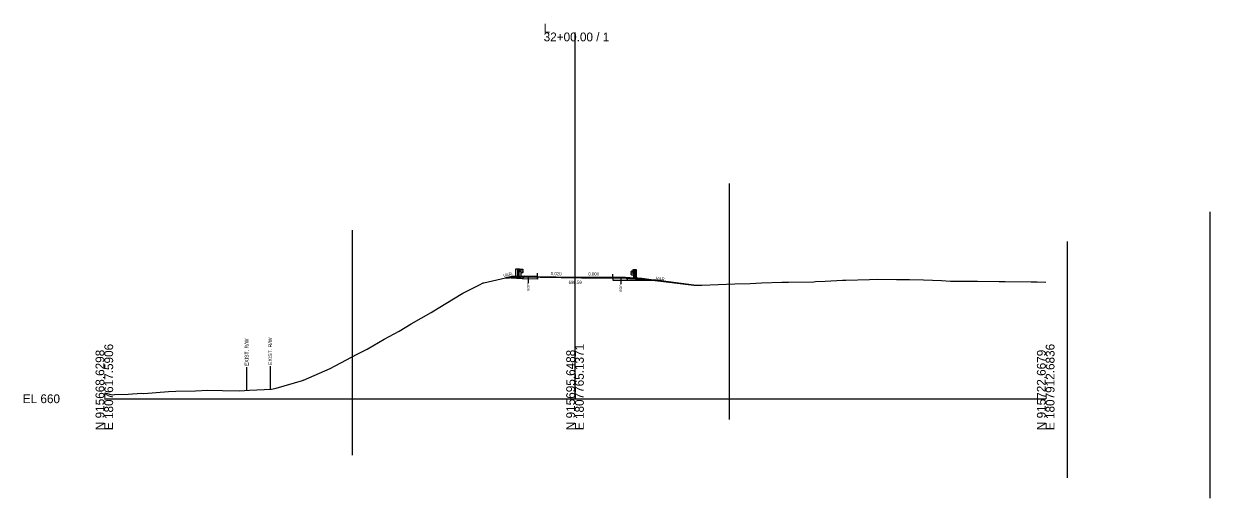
# Model space of a CAD drawing. Extents: x -26 to 1352, y -510 to 9596.
# Drawn here: x 974.3 to 1352.4, y 7968.3 to 8119.4 of the extents above; entities that cross this region are included whole.
import ezdxf

# ---------------------------------------------------------------- set-up
doc = ezdxf.new("R2010")
doc.units = 0
for name, color, linetype in [('Exist Cross Section Cell', 7, 'Continuous'), ('Exist XS Center Line Elevation Label', 7, 'Continuous'), ('Exist XS Ground Line', 7, 'Continuous'), ('Old_Level_10', 7, 'Continuous'), ('Prop XS Ditch Slope Text', 7, 'Continuous'), ('Prop XS Dump Level', 7, 'Continuous'), ('Prop XS Earthwork Shape', 7, 'Continuous'), ('Prop XS EOT Tick Mark', 7, 'Continuous'), ('Prop XS Exc Vertical Line 1', 7, 'Continuous'), ('Prop XS Exc Vertical Line 2', 7, 'Continuous'), ('Prop XS Exc Vertical Line 3', 7, 'Continuous'), ('Prop XS Exc Vertical Line 4', 7, 'Continuous'), ('Prop XS Finish Grade', 7, 'Continuous'), ('Prop XS Finish Grade Earthwork', 7, 'Continuous'), ('Prop XS Finish Grade Paved Shoulder', 7, 'Continuous'), ('Prop XS Finish Grade Pavement', 7, 'Continuous'), ('Prop XS Guardrail', 7, 'Continuous'), ('Prop XS Pvmt Edge Slope', 7, 'Continuous'), ('Prop XS SE Text', 7, 'Continuous'), ('Prop XS Subgrade Earthwork', 7, 'Continuous'), ('Scratch_Level_6', 7, 'Continuous')]:
    doc.layers.add(name, color=color, linetype=linetype)

msp = doc.modelspace()

# ---------------------------------------------------------------- linework, layer by layer
at = {"layer": 'Exist Cross Section Cell'}
for p, q in [((1150, 8000), (1150, 8116.63)), ((1000, 8000), (1150, 8000)), ((1150, 8000), (1300, 8000))]:
    msp.add_line(p, q, dxfattribs=at)
at = {"layer": 'Exist XS Ground Line'}
msp.add_lwpolyline([(1000, 8001.87), (1002.45, 8001.25), (1003.25, 8001.33), (1007.61, 8001.46), (1011.84, 8001.81), (1012.62, 8001.65), (1020.43, 8002.35), (1022.78, 8002.43), (1029.03, 8002.53), (1032.95, 8002.72), (1037.62, 8002.61), (1043.11, 8002.52), (1046.21, 8002.72), (1053.28, 8003.05), (1054.8, 8003.35), (1063.12, 8005.82), (1063.4, 8005.9), (1063.45, 8005.92), (1071.99, 8009.61), (1073.61, 8010.46), (1080.58, 8014.16), (1083.78, 8015.79), (1089.18, 8018.94), (1093.95, 8021.58), (1097.77, 8023.82), (1104.11, 8027.48), (1106.36, 8028.84), (1114.28, 8033.66), (1119.55, 8036.25), (1120.71, 8036.87), (1120.92, 8036.92), (1127.82, 8038.47), (1128.23, 8038.51), (1128.56, 8038.52), (1128.66, 8038.53), (1128.81, 8038.53), (1128.84, 8038.54), (1129.09, 8038.55), (1129.56, 8038.58), (1130.68, 8038.64), (1135.06, 8038.88), (1135.2, 8038.87), (1136.36, 8038.84), (1136.7, 8038.83), (1137.13, 8038.83), (1138.65, 8038.78), (1138.91, 8038.77), (1139.18, 8038.77), (1140.62, 8038.76), (1141.45, 8038.76), (1143.47, 8038.71), (1143.99, 8038.69), (1145.62, 8038.66), (1146.54, 8038.65), (1147.87, 8038.63), (1149.07, 8038.62), (1149.52, 8038.6), (1149.89, 8038.59), (1150, 8038.59), (1151.18, 8038.57), (1151.61, 8038.57), (1152.05, 8038.56), (1154.15, 8038.56), (1154.49, 8038.56), (1156.7, 8038.56), (1158.51, 8038.54), (1159.24, 8038.53), (1161.26, 8038.54), (1161.97, 8038.55), (1161.97, 8038.55), (1162.87, 8038.55), (1164.6, 8038.55), (1165.66, 8038.47), (1166.8, 8038.39), (1167.41, 8038.34), (1169.23, 8038.22), (1175.51, 8037.67), (1187.86, 8036.19), (1190.39, 8036.21), (1195.61, 8036.38), (1200.88, 8036.6), (1205.78, 8036.74), (1209.47, 8036.87), (1215.94, 8037.1), (1218.07, 8037.1), (1226.11, 8037.27), (1226.66, 8037.3), (1229.67, 8037.46), (1235.25, 8037.79), (1236.27, 8037.79), (1243.85, 8037.99), (1246.44, 8038.06), (1252.44, 8038.03), (1256.61, 8037.96), (1261.03, 8037.88), (1266.77, 8037.69), (1269.62, 8037.5), (1276.94, 8037.47), (1278.22, 8037.46), (1285.19, 8037.34), (1286.81, 8037.31), (1287.11, 8037.3), (1295.4, 8037.21), (1297.27, 8037.19), (1300, 8037.13)], dxfattribs=at)
at = {"layer": 'Old_Level_10'}
for p, q in [((1135.06, 8038.88), (1135.06, 8036.83)), ((1164.6, 8038.55), (1164.6, 8036.5)), ((1045.35, 8010.06), (1045.35, 8002.66)), ((1052.86, 8010.43), (1052.86, 8003.03))]:
    msp.add_line(p, q, dxfattribs=at)
at = {"layer": 'Prop XS Dump Level'}
for p, q in [((1150, 8038.6), (1138, 8038.84)), ((1138, 8038.84), (1138, 8038.8)), ((1162, 8038.6), (1150, 8038.6)), ((1162, 8038.55), (1162, 8038.6))]:
    msp.add_line(p, q, dxfattribs=at)
msp.add_lwpolyline([(1138, 8038.8), (1138.65, 8038.78), (1138.91, 8038.77), (1139.18, 8038.77), (1140.62, 8038.76), (1141.45, 8038.76), (1143.47, 8038.71), (1143.99, 8038.69), (1145.62, 8038.66), (1146.54, 8038.65), (1147.87, 8038.63), (1149.07, 8038.62), (1149.52, 8038.6), (1149.89, 8038.59), (1150, 8038.59), (1151.18, 8038.57), (1151.61, 8038.57), (1152.05, 8038.56), (1154.15, 8038.56), (1154.49, 8038.56), (1156.7, 8038.56), (1158.51, 8038.54), (1159.24, 8038.53), (1161.26, 8038.54), (1161.97, 8038.55), (1161.97, 8038.55), (1162, 8038.55)], dxfattribs=at)
at = {"layer": 'Prop XS Earthwork Shape'}
for points in [[(1128.84, 8038.54), (1129.09, 8038.55), (1129.56, 8038.58), (1130.68, 8038.64), (1135.06, 8038.88), (1135.2, 8038.87), (1136.36, 8038.84), (1136.7, 8038.83), (1137.13, 8038.83), (1138, 8038.8), (1138, 8038.05), (1133.1, 8038.15), (1127.82, 8038.47), (1128.23, 8038.51), (1128.56, 8038.52), (1128.66, 8038.53), (1128.81, 8038.53)], [(1138, 8038.05), (1133.1, 8038.15), (1127.82, 8038.47), (1128.23, 8038.51), (1128.56, 8038.52), (1128.66, 8038.53), (1128.81, 8038.53), (1128.84, 8038.54), (1129.09, 8038.55), (1129.56, 8038.58), (1130.68, 8038.64), (1135.06, 8038.88), (1135.2, 8038.87), (1136.36, 8038.84), (1136.7, 8038.83), (1137.13, 8038.83), (1138, 8038.8)], [(1128.81, 8038.53), (1128.84, 8038.54), (1129.09, 8038.55), (1129.56, 8038.58), (1130.68, 8038.64), (1135.06, 8038.88), (1135.2, 8038.87), (1136.36, 8038.84), (1136.7, 8038.83), (1137.13, 8038.83), (1138, 8038.8), (1138, 8038.05), (1133.1, 8038.15), (1127.82, 8038.47), (1128.23, 8038.51), (1128.56, 8038.52), (1128.66, 8038.53)], [(1128.81, 8038.53), (1128.84, 8038.54), (1129.09, 8038.55), (1129.56, 8038.58), (1130.68, 8038.64), (1135.06, 8038.88), (1135.2, 8038.87), (1136.36, 8038.84), (1136.7, 8038.83), (1137.13, 8038.83), (1138, 8038.8), (1138, 8038.05), (1133.1, 8038.15), (1127.82, 8038.47), (1128.23, 8038.51), (1128.56, 8038.52), (1128.66, 8038.53)], [(1128.84, 8038.54), (1129.09, 8038.55), (1129.56, 8038.58), (1130.68, 8038.64), (1135.06, 8038.88), (1135.2, 8038.87), (1136.36, 8038.84), (1136.7, 8038.83), (1137.13, 8038.83), (1138, 8038.8), (1138, 8038.05), (1133.1, 8038.15), (1127.82, 8038.47), (1128.23, 8038.51), (1128.56, 8038.52), (1128.66, 8038.53), (1128.81, 8038.53)], [(1162, 8038.55), (1162, 8037.81), (1166.92, 8037.81), (1173.92, 8037.81), (1169.23, 8038.22), (1167.41, 8038.34), (1166.8, 8038.39), (1165.66, 8038.47), (1164.6, 8038.55), (1162.87, 8038.55)], [(1162, 8038.55), (1162, 8037.81), (1166.92, 8037.81), (1173.92, 8037.81), (1169.23, 8038.22), (1167.41, 8038.34), (1166.8, 8038.39), (1165.66, 8038.47), (1164.6, 8038.55), (1162.87, 8038.55)], [(1166.92, 8037.81), (1173.92, 8037.81), (1169.23, 8038.22), (1167.41, 8038.34), (1166.8, 8038.39), (1165.66, 8038.47), (1164.6, 8038.55), (1162.87, 8038.55), (1162, 8038.55), (1162, 8037.81)], [(1162, 8038.55), (1162, 8037.81), (1166.92, 8037.81), (1173.92, 8037.81), (1169.23, 8038.22), (1167.41, 8038.34), (1166.8, 8038.39), (1165.66, 8038.47), (1164.6, 8038.55), (1162.87, 8038.55)], [(1175.51, 8037.67), (1187.86, 8036.19), (1175.79, 8037.81), (1173.92, 8037.81)], [(1175.79, 8037.81), (1187.86, 8036.19), (1175.51, 8037.67), (1173.92, 8037.81)], [(1175.79, 8037.81), (1187.86, 8036.19), (1175.51, 8037.67), (1173.92, 8037.81)], [(1175.79, 8037.81), (1187.86, 8036.19), (1175.51, 8037.67), (1173.92, 8037.81)], [(1173.92, 8037.81), (1175.79, 8037.81), (1187.86, 8036.19), (1175.51, 8037.67)]]:
    msp.add_lwpolyline(points, close=True, dxfattribs=at)
at = {"layer": 'Prop XS EOT Tick Mark'}
for p, q in [((1138, 8038.97), (1138, 8039.97)), ((1162, 8038.73), (1162, 8039.73))]:
    msp.add_line(p, q, dxfattribs=at)
at = {"layer": 'Prop XS Exc Vertical Line 1'}
msp.add_line((1079.04, 7981.99), (1079.04, 8053.65), dxfattribs=at)
at = {"layer": 'Prop XS Exc Vertical Line 2'}
msp.add_line((1199.25, 7993.36), (1199.25, 8068.59), dxfattribs=at)
at = {"layer": 'Prop XS Exc Vertical Line 3'}
msp.add_line((1306.96, 7974.83), (1306.96, 8050.07), dxfattribs=at)
at = {"layer": 'Prop XS Exc Vertical Line 4'}
msp.add_line((1352.44, 7968.31), (1352.44, 8059.51), dxfattribs=at)
at = {"layer": 'Prop XS Finish Grade'}
for p, q in [((1129.44, 8038.87), (1127.82, 8038.47)), ((1132.43, 8038.99), (1129.44, 8038.87)), ((1132.43, 8038.99), (1130, 8038.89)), ((1134, 8039.05), (1132.43, 8038.99)), ((1166, 8038.73), (1167.57, 8038.64)), ((1167.57, 8038.64), (1170, 8038.49)), ((1170, 8038.49), (1171.32, 8038.41)), ((1171.32, 8038.41), (1175.79, 8037.81))]:
    msp.add_line(p, q, dxfattribs=at)
at = {"layer": 'Prop XS Finish Grade Earthwork'}
msp.add_line((1175.79, 8037.81), (1187.86, 8036.19), dxfattribs=at)
at = {"layer": 'Prop XS Finish Grade Paved Shoulder'}
for p, q in [((1138, 8038.97), (1134, 8039.05)), ((1162, 8038.73), (1166, 8038.73))]:
    msp.add_line(p, q, dxfattribs=at)
at = {"layer": 'Prop XS Finish Grade Pavement'}
for p, q in [((1138, 8038.97), (1150, 8038.73)), ((1150, 8038.73), (1162, 8038.73))]:
    msp.add_line(p, q, dxfattribs=at)
at = {"layer": 'Prop XS Guardrail'}
for p, q in [((1131.15, 8038.92), (1131.15, 8041.42)), ((1131.15, 8041.42), (1131.65, 8041.42)), ((1131.65, 8041.42), (1131.65, 8038.92)), ((1131.65, 8041.42), (1132.15, 8041.42)), ((1132.15, 8040.29), (1131.65, 8040.29)), ((1132.15, 8041.42), (1132.44, 8041.22)), ((1132.44, 8041.1), (1132.15, 8040.9)), ((1132.15, 8040.9), (1132.15, 8040.81)), ((1132.15, 8040.81), (1132.44, 8040.61)), ((1132.44, 8040.49), (1132.15, 8040.29)), ((1132.44, 8041.22), (1132.47, 8041.16)), ((1132.47, 8041.16), (1132.44, 8041.1)), ((1132.44, 8040.61), (1132.47, 8040.55)), ((1132.47, 8040.55), (1132.44, 8040.49)), ((1168.32, 8040.86), (1168.29, 8040.8)), ((1168.29, 8040.8), (1168.32, 8040.74)), ((1168.32, 8040.24), (1168.29, 8040.18)), ((1168.29, 8040.18), (1168.32, 8040.12)), ((1168.61, 8041.06), (1168.32, 8040.86)), ((1168.32, 8040.74), (1168.61, 8040.54)), ((1168.61, 8040.44), (1168.32, 8040.24)), ((1168.32, 8040.12), (1168.61, 8039.92)), ((1169.11, 8041.06), (1168.61, 8041.06)), ((1168.61, 8040.54), (1168.61, 8040.44)), ((1168.61, 8039.92), (1169.11, 8039.92)), ((1169.61, 8041.06), (1169.11, 8041.06)), ((1169.11, 8041.06), (1169.11, 8038.56)), ((1169.61, 8038.56), (1169.61, 8041.06))]:
    msp.add_line(p, q, dxfattribs=at)
at = {"layer": 'Prop XS Pvmt Edge Slope'}
for p, q in [((1134, 8039.05), (1133.1, 8038.15)), ((1166, 8038.73), (1166.92, 8037.81))]:
    msp.add_line(p, q, dxfattribs=at)
at = {"layer": 'Prop XS Subgrade Earthwork'}
for p, q in [((1133.1, 8038.15), (1127.82, 8038.47)), ((1138, 8038.05), (1133.1, 8038.15)), ((1138, 8038.05), (1138, 8038.8)), ((1162, 8038.55), (1162, 8037.81)), ((1162, 8037.81), (1166.92, 8037.81)), ((1166.92, 8037.81), (1175.79, 8037.81))]:
    msp.add_line(p, q, dxfattribs=at)
at = {"layer": 'Scratch_Level_6'}
for p, q in [((1132.22, 8038.73), (1132.22, 8041.23)), ((1132.22, 8041.23), (1132.72, 8041.23)), ((1132.72, 8041.23), (1132.72, 8038.73)), ((1132.72, 8041.23), (1133.22, 8041.23)), ((1133.22, 8040.1), (1132.72, 8040.1)), ((1133.22, 8041.23), (1133.51, 8041.03)), ((1133.51, 8040.91), (1133.22, 8040.71)), ((1133.22, 8040.71), (1133.22, 8040.62)), ((1133.22, 8040.62), (1133.51, 8040.42)), ((1133.51, 8040.3), (1133.22, 8040.1)), ((1133.51, 8041.03), (1133.54, 8040.97)), ((1133.54, 8040.97), (1133.51, 8040.91)), ((1133.51, 8040.42), (1133.54, 8040.36)), ((1133.54, 8040.36), (1133.51, 8040.3)), ((1167.82, 8040.45), (1167.79, 8040.39)), ((1167.79, 8040.39), (1167.82, 8040.33)), ((1167.82, 8039.83), (1167.79, 8039.77)), ((1167.79, 8039.77), (1167.82, 8039.71)), ((1168.11, 8040.65), (1167.82, 8040.45)), ((1167.82, 8040.33), (1168.11, 8040.13)), ((1168.11, 8040.03), (1167.82, 8039.83)), ((1167.82, 8039.71), (1168.11, 8039.51)), ((1168.61, 8040.65), (1168.11, 8040.65)), ((1168.11, 8040.13), (1168.11, 8040.03)), ((1168.11, 8039.51), (1168.61, 8039.51)), ((1169.11, 8040.65), (1168.61, 8040.65)), ((1168.61, 8040.65), (1168.61, 8038.15)), ((1169.11, 8038.15), (1169.11, 8040.65))]:
    msp.add_line(p, q, dxfattribs=at)

# ---------------------------------------------------------------- texts
at = {"layer": 'Exist Cross Section Cell'}
for s, p in [('L', (1140, 8116.63)), ('32+00.00 / 1', (1140, 8113.83)), ('EL 660', (974, 7998.6))]:
    msp.add_text(s, height=2.8, dxfattribs=at).set_placement(p)
for s, p in [('E 1807617.5906', (1002.8, 7990)), ('E 1807765.1371', (1152.8, 7990)), ('E 1807912.6836', (1302.8, 7990)), ('N 915668.6298', (1000, 7990)), ('N 915695.6488', (1150, 7990)), ('N 915722.6679', (1300, 7990))]:
    msp.add_text(s, height=2.8, rotation=90, dxfattribs=at).set_placement(p)
at = {"layer": 'Exist XS Center Line Elevation Label'}
msp.add_text('698.59', height=1, dxfattribs=at).set_placement((1147.95, 8036.59))
at = {"layer": 'Old_Level_10'}
for s, height, p in [('EOP', 0.787, (1135.46, 8034.43)), ('EOP', 0.787, (1164.99, 8034.1)), ('EXIST. R/W', 1.181, (1045.94, 8010.37)), ('EXIST. R/W', 1.181, (1053.45, 8010.73))]:
    msp.add_text(s, height=height, rotation=90, dxfattribs=at).set_placement(p)
at = {"layer": 'Prop XS Ditch Slope Text'}
for rotation, p in [(14.0362, (1127.21, 8038.66)), (352.6732, (1175.68, 8037.9))]:
    msp.add_text('VAR.', height=1, rotation=rotation, dxfattribs=at).set_placement(p)
at = {"layer": 'Prop XS SE Text'}
for s, rotation, p in [('0.020', 358.8542, (1142.25, 8039.38)), ('0.000', 360, (1154.25, 8039.23))]:
    msp.add_text(s, height=1, rotation=rotation, dxfattribs=at).set_placement(p)

doc.saveas('drawing.dxf')
